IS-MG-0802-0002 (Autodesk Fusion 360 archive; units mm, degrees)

design "IS-MG-0802-0003" references "4M screw", "5 holes POWER", "SFP SLOT", "Digitus_DN-651107_LAN-Switch", "DIP Switch", "4 ports ethernet", "1 ports ethernet"
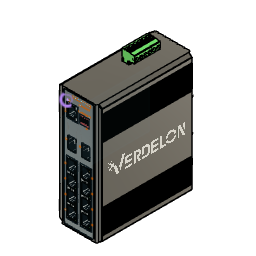
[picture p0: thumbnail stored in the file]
sketch "Sketch1" plane through (0, 0, 0) normal (0, 1, 0) x axis (1, 0, 0)
  line L1 (46, 0) -> (4, 0)
  line L2 (50, -137) -> (50, -3)
  line L3 (4, -140) -> (46, -140)
  line L4 (0, -3) -> (0, -137)
  line L5 (0, -137) -> (4, -140)
  line L6 (46, -140) -> (50, -137)
  line L7 (50, -3) -> (46, 0)
  line L8 (0, -3) -> (4, 0)
  point P1 (0, 0)
  point P2 (0, 0)
  point P5 (0, -140)
  point P4 (50, -140)
  point P3 (50, 0)
  point P6 (4, -140)
  point P7 (0, -137)
  point P8 (50, -137)
  point P9 (46, -140)
  point P10 (46, 0)
  point P11 (50, -3)
  point P12 (4, 0)
  point P13 (0, -3)
  horizontal L1
  vertical L2
  horizontal L3
  vertical L4
  coincident P1 P2
  coincident P5 L3
  coincident P5 L4
  coincident P4 L2
  coincident P4 L3
  coincident P3 L1
  coincident P3 L2
  coincident P2 L1
  coincident P2 L4
  dimension "d1" distance P2 P5 = 140
  dimension "d2" distance P2 P3 = 50
  dimension "d3" distance P5 P6 = 4
  dimension "d4" distance P5 P7 = 3
  dimension "d5" distance P4 P8 = 3
  dimension "d6" distance P4 P9 = 4
  dimension "d7" distance P3 P10 = 4
  dimension "d8" distance P3 P11 = 3
  dimension "d9" distance P2 P12 = 4
  dimension "d10" distance P2 P13 = 3
extrude "Extrude1" new body sketch "Sketch1" along normal blind 110
sketch "Sketch2" plane through (0, 0, 0) normal (0, -1, 0) x axis (1, 0, 0)
  line L1 (46, 0) -> (4, 0)
  line L2 (50, 3) -> (46, 0)
  line L3 (50, 137) -> (50, 3)
  line L4 (46, 140) -> (50, 137)
  line L5 (4, 140) -> (46, 140)
  line L6 (0, 137) -> (4, 140)
  line L7 (0, 3) -> (0, 137)
  line L8 (4, 0) -> (0, 3)
  line L9 (4, 0) -> (4, 140)
  line L10 (0, 137) -> (0, 3)
  line L11 (0, 137) -> (4, 140)
  line L12 (4, 0) -> (0, 3)
  line L13 (25, 152.2734) -> (25, 140)
  line L14 (50, 137) -> (46, 140)
  line L15 (46, 0) -> (50, 3)
  line L16 (46, 0) -> (46, 140)
  line L17 (50, 3) -> (50, 137)
  line L18 (46, 0) -> (50, 3)
  line L19 (50, 137) -> (50, 3)
  line L20 (50, 137) -> (46, 140)
  point P7 (4, 140)
  point P10 (4, 140)
  point P2 (4, 0)
  point P11 (4, 0)
  point P9 (0, 3)
  point P12 (0, 3)
  point P8 (0, 137)
  point P13 (0, 137)
  point P14 (0, 3)
  point P15 (25, 140)
  point P1 (0, 0)
  point P18 (50, 0)
  point P19 (46, 0)
  point P25 (46, 140)
  point P24 (50, 137)
  point P26 (50, 3)
  point P17 (46, 140)
  point P21 (46, 0)
  point P22 (50, 3)
  point P23 (50, 137)
  point P20 (50, 3)
  coincident P7 P10
  coincident P2 P11
  coincident P9 P12
  coincident P8 P13
  coincident P9 P14
  midpoint L5 P15
  perpendicular L5 L13
  symmetric P1 L13 P18
  symmetric P2 L13 P19
  symmetric P7 L13 P25
  symmetric P8 L13 P24
  symmetric P9 L13 P26
  symmetric P10 L13 P17
  symmetric P11 L13 P21
  symmetric P12 L13 P22
  symmetric P13 L13 P23
  symmetric P14 L13 P20
extrude "Extrude2" cut sketch "Sketch2" profile of L2 L3 L4 L6 L7 L8 L9 L10 L11 L12 L14 L15 L16 L17 L18 L19 L20 against normal blind 2
sketch "Sketch3" plane through (0, 110, 0) normal (0, 1, 0) x axis (-1, 0, 0)
  line L1 (-4, 0) -> (-46, 0)
  line L2 (0, 3) -> (-4, 0)
  line L3 (0, 137) -> (0, 3)
  line L4 (-4, 140) -> (0, 137)
  line L5 (-46, 140) -> (-4, 140)
  line L6 (-50, 137) -> (-46, 140)
  line L7 (-50, 3) -> (-50, 137)
  line L8 (-46, 0) -> (-50, 3)
  line L9 (-46, 0) -> (-46, 140)
  line L10 (-50, 3) -> (-46, 0)
  line L11 (-50, 137) -> (-50, 3)
  line L12 (-46, 140) -> (-50, 137)
  line L13 (-25, 146.5835) -> (-25, 140)
  line L14 (-4, 0) -> (0, 3)
  line L15 (0, 3) -> (-4, 0)
  line L16 (-4, 140) -> (0, 137)
  line L17 (0, 137) -> (-4, 140)
  line L18 (0, 3) -> (0, 137)
  line L19 (0, 137) -> (0, 3)
  line L20 (-4, 0) -> (-4, 140)
  point P7 (-46, 140)
  point P10 (-46, 140)
  point P2 (-46, 0)
  point P11 (-46, 0)
  point P9 (-50, 3)
  point P12 (-50, 3)
  point P8 (-50, 137)
  point P13 (-50, 137)
  point P14 (-25, 140)
  point P16 (-4, 0)
  point P19 (-4, 140)
  point P18 (0, 137)
  point P21 (0, 3)
  point P23 (-4, 140)
  point P22 (-4, 0)
  point P20 (0, 3)
  point P17 (0, 137)
  coincident P7 P10
  coincident P2 P11
  coincident P9 P12
  coincident P8 P13
  midpoint L5 P14
  perpendicular L5 L13
  symmetric P2 L13 P16
  symmetric P7 L13 P19
  symmetric P8 L13 P18
  symmetric P9 L13 P21
  symmetric P10 L13 P23
  symmetric P11 L13 P22
  symmetric P12 L13 P20
  symmetric P13 L13 P17
extrude "Extrude3" cut sketch "Sketch3" profile of L2 L3 L4 L6 L7 L8 L9 L10 L11 L12 L14 L15 L16 L17 L18 L19 L20 against normal blind 2
sketch "Sketch6" plane through (0, 2, 0) normal (0, -1, 0) x axis (1, 0, 0)
  line L1 (0, 137) -> (4, 140)
  line L2 (0, 3) -> (0, 137)
  line L3 (4, 0) -> (0, 3)
  line L4 (4, 140) -> (4, 0)
  line L5 (-20, 70) -> (0, 70)
  line L6 (50, 137) -> (0, 137)
  line L7 (25, 148.9841) -> (25, 137)
  line L8 (0, 130.5) -> (0, 131.5)
  line L9 (0, 129.4815) -> (0, 130.4815)
  line L10 (0, 128.463) -> (0, 129.463)
  line L11 (0, 127.4444) -> (0, 128.4444)
  line L12 (0, 126.4259) -> (0, 127.4259)
  line L13 (0, 125.4074) -> (0, 126.4074)
  line L14 (0, 124.3889) -> (0, 125.3889)
  line L15 (0, 123.3704) -> (0, 124.3704)
  line L16 (0, 122.3519) -> (0, 123.3519)
  line L17 (0, 121.3333) -> (0, 122.3333)
  line L18 (0, 120.3148) -> (0, 121.3148)
  line L19 (0, 119.2963) -> (0, 120.2963)
  line L20 (0, 118.2778) -> (0, 119.2778)
  line L21 (0, 117.2593) -> (0, 118.2593)
  line L22 (0, 116.2407) -> (0, 117.2407)
  line L23 (0, 115.2222) -> (0, 116.2222)
  line L24 (0, 114.2037) -> (0, 115.2037)
  line L25 (0, 113.1852) -> (0, 114.1852)
  line L26 (0, 112.1667) -> (0, 113.1667)
  line L27 (0, 111.1481) -> (0, 112.1481)
  line L28 (0, 110.1296) -> (0, 111.1296)
  line L29 (0, 109.1111) -> (0, 110.1111)
  line L30 (0, 108.0926) -> (0, 109.0926)
  line L31 (0, 107.0741) -> (0, 108.0741)
  line L32 (0, 106.0556) -> (0, 107.0556)
  line L33 (0, 105.037) -> (0, 106.037)
  line L34 (0, 104.0185) -> (0, 105.0185)
  line L35 (0, 103) -> (0, 104)
  line L36 (0, 25.7963) -> (0, 24.7963)
  line L37 (0, 13.5741) -> (0, 12.5741)
  line L38 (0, 28.8519) -> (0, 27.8519)
  line L39 (0, 27.8333) -> (0, 26.8333)
  line L40 (0, 34.963) -> (0, 33.963)
  line L41 (0, 32.9259) -> (0, 31.9259)
  line L42 (0, 30.8889) -> (0, 29.8889)
  line L43 (0, 23.7593) -> (0, 22.7593)
  line L44 (0, 29.8704) -> (0, 28.8704)
  line L45 (0, 37) -> (0, 36)
  line L46 (0, 10.5185) -> (0, 9.5185)
  line L47 (0, 31.9074) -> (0, 30.9074)
  line L48 (0, 19.6852) -> (0, 18.6852)
  line L49 (0, 35.9815) -> (0, 34.9815)
  line L50 (0, 26.8148) -> (0, 25.8148)
  line L51 (0, 16.6296) -> (0, 15.6296)
  line L52 (0, 22.7407) -> (0, 21.7407)
  line L53 (0, 33.9444) -> (0, 32.9444)
  line L54 (0, 9.5) -> (0, 8.5)
  line L55 (0, 20.7037) -> (0, 19.7037)
  line L56 (0, 18.6667) -> (0, 17.6667)
  line L57 (0, 12.5556) -> (0, 11.5556)
  line L58 (0, 15.6111) -> (0, 14.6111)
  line L59 (0, 14.5926) -> (0, 13.5926)
  line L60 (0, 11.537) -> (0, 10.537)
  line L61 (0, 21.7222) -> (0, 20.7222)
  line L62 (0, 24.7778) -> (0, 23.7778)
  line L63 (0, 17.6481) -> (0, 16.6481)
  line L64 (50, 28.8519) -> (50, 27.8519)
  line L65 (50, 32.9259) -> (50, 31.9259)
  line L66 (50, 22.7407) -> (50, 21.7407)
  line L67 (50, 31.9074) -> (50, 30.9074)
  line L68 (50, 21.7222) -> (50, 20.7222)
  line L69 (50, 29.8704) -> (50, 28.8704)
  line L70 (50, 30.8889) -> (50, 29.8889)
  line L71 (50, 25.7963) -> (50, 24.7963)
  line L72 (50, 9.5) -> (50, 8.5)
  line L73 (50, 33.9444) -> (50, 32.9444)
  line L74 (50, 24.7778) -> (50, 23.7778)
  line L75 (50, 11.537) -> (50, 10.537)
  line L76 (50, 35.9815) -> (50, 34.9815)
  line L77 (50, 23.7593) -> (50, 22.7593)
  line L78 (50, 20.7037) -> (50, 19.7037)
  line L79 (50, 34.963) -> (50, 33.963)
  line L80 (50, 26.8148) -> (50, 25.8148)
  line L81 (50, 27.8333) -> (50, 26.8333)
  line L82 (50, 18.6667) -> (50, 17.6667)
  line L83 (50, 37) -> (50, 36)
  line L84 (50, 19.6852) -> (50, 18.6852)
  line L85 (50, 15.6111) -> (50, 14.6111)
  line L86 (50, 16.6296) -> (50, 15.6296)
  line L87 (50, 10.5185) -> (50, 9.5185)
  line L88 (50, 17.6481) -> (50, 16.6481)
  line L89 (50, 12.5556) -> (50, 11.5556)
  line L90 (50, 13.5741) -> (50, 12.5741)
  line L91 (50, 14.5926) -> (50, 13.5926)
  line L92 (50, 103) -> (50, 104)
  line L93 (50, 104.0185) -> (50, 105.0185)
  line L94 (50, 105.037) -> (50, 106.037)
  line L95 (50, 121.3333) -> (50, 122.3333)
  line L96 (50, 130.5) -> (50, 131.5)
  line L97 (50, 120.3148) -> (50, 121.3148)
  line L98 (50, 118.2778) -> (50, 119.2778)
  line L99 (50, 126.4259) -> (50, 127.4259)
  line L100 (50, 110.1296) -> (50, 111.1296)
  line L101 (50, 114.2037) -> (50, 115.2037)
  line L102 (50, 111.1481) -> (50, 112.1481)
  line L103 (50, 123.3704) -> (50, 124.3704)
  line L104 (50, 115.2222) -> (50, 116.2222)
  line L105 (50, 116.2407) -> (50, 117.2407)
  line L106 (50, 124.3889) -> (50, 125.3889)
  line L107 (50, 127.4444) -> (50, 128.4444)
  line L108 (50, 119.2963) -> (50, 120.2963)
  line L109 (50, 109.1111) -> (50, 110.1111)
  line L110 (50, 113.1852) -> (50, 114.1852)
  line L111 (50, 128.463) -> (50, 129.463)
  line L112 (50, 125.4074) -> (50, 126.4074)
  line L113 (50, 112.1667) -> (50, 113.1667)
  line L114 (50, 107.0741) -> (50, 108.0741)
  line L115 (50, 108.0926) -> (50, 109.0926)
  line L116 (50, 129.4815) -> (50, 130.4815)
  line L117 (50, 122.3519) -> (50, 123.3519)
  line L118 (50, 117.2593) -> (50, 118.2593)
  line L119 (50, 106.0556) -> (50, 107.0556)
  arc A1 centre (0, 131) radius 0.5 clockwise from (0, 131.5) to (0, 130.5)
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  point P6 (0, 70)
  point P3 (0, 137)
  point P8 (0, 137)
  point P10 (25, 137)
  point P12 (0, 131)
  point P13 (0, 131.5)
  point P14 (0, 130.5)
  point P149 (0, 8.5)
  point P159 (0, 9.5)
  point P16 (0, 129.4815)
  point P137 (0, 10.5185)
  point P17 (0, 130.4815)
  point P132 (0, 9.5185)
  point P19 (0, 128.463)
  point P147 (0, 11.537)
  point P20 (0, 129.463)
  point P176 (0, 10.537)
  point P22 (0, 127.4444)
  point P112 (0, 12.5556)
  point P23 (0, 128.4444)
  point P110 (0, 11.5556)
  point P25 (0, 126.4259)
  point P99 (0, 13.5741)
  point P26 (0, 127.4259)
  point P165 (0, 12.5741)
  point P28 (0, 125.4074)
  point P157 (0, 14.5926)
  point P29 (0, 126.4074)
  point P163 (0, 13.5926)
  point P31 (0, 124.3889)
  point P166 (0, 15.6111)
  point P32 (0, 125.3889)
  point P160 (0, 14.6111)
  point P34 (0, 123.3704)
  point P155 (0, 16.6296)
  point P35 (0, 124.3704)
  point P161 (0, 15.6296)
  point P37 (0, 122.3519)
  point P156 (0, 17.6481)
  point P38 (0, 123.3519)
  point P97 (0, 16.6481)
  point P40 (0, 121.3333)
  point P98 (0, 18.6667)
  point P41 (0, 122.3333)
  point P115 (0, 17.6667)
  point P43 (0, 120.3148)
  point P109 (0, 19.6852)
  point P44 (0, 121.3148)
  point P143 (0, 18.6852)
  point P46 (0, 119.2963)
  point P139 (0, 20.7037)
  point P47 (0, 120.2963)
  point P124 (0, 19.7037)
  point P49 (0, 118.2778)
  point P123 (0, 21.7222)
  point P50 (0, 119.2778)
  point P108 (0, 20.7222)
  point P52 (0, 117.2593)
  point P105 (0, 22.7407)
  point P53 (0, 118.2593)
  point P167 (0, 21.7407)
  point P55 (0, 116.2407)
  point P106 (0, 23.7593)
  point P56 (0, 117.2407)
  point P107 (0, 22.7593)
  point P58 (0, 115.2222)
  point P104 (0, 24.7778)
  point P59 (0, 116.2222)
  point P96 (0, 23.7778)
  point P61 (0, 114.2037)
  point P130 (0, 25.7963)
  point P62 (0, 115.2037)
  point P125 (0, 24.7963)
  point P64 (0, 113.1852)
  point P126 (0, 26.8148)
  point P65 (0, 114.1852)
  point P121 (0, 25.8148)
  point P67 (0, 112.1667)
  point P127 (0, 27.8333)
  point P68 (0, 113.1667)
  point P134 (0, 26.8333)
  point P70 (0, 111.1481)
  point P138 (0, 28.8519)
  point P71 (0, 112.1481)
  point P140 (0, 27.8519)
  point P73 (0, 110.1296)
  point P142 (0, 29.8704)
  point P74 (0, 111.1296)
  point P133 (0, 28.8704)
  point P76 (0, 109.1111)
  point P154 (0, 30.8889)
  point P77 (0, 110.1111)
  point P151 (0, 29.8889)
  point P79 (0, 108.0926)
  point P153 (0, 31.9074)
  point P80 (0, 109.0926)
  point P168 (0, 30.9074)
  point P82 (0, 107.0741)
  point P171 (0, 32.9259)
  point P83 (0, 108.0741)
  point P175 (0, 31.9259)
  point P85 (0, 106.0556)
  point P172 (0, 33.9444)
  point P86 (0, 107.0556)
  point P146 (0, 32.9444)
  point P88 (0, 105.037)
  point P141 (0, 34.963)
  point P89 (0, 106.037)
  point P131 (0, 33.963)
  point P91 (0, 104.0185)
  point P129 (0, 35.9815)
  point P92 (0, 105.0185)
  point P119 (0, 34.9815)
  point P94 (0, 103)
  point P179 (0, 37)
  point P95 (0, 104)
  point P103 (0, 36)
  point P331 (50, 131.5)
  point P289 (50, 130.5)
  point P341 (50, 129.4815)
  point P324 (50, 130.4815)
  point P320 (50, 128.463)
  point P325 (50, 129.463)
  point P282 (50, 127.4444)
  point P294 (50, 128.4444)
  point P300 (50, 126.4259)
  point P298 (50, 127.4259)
  point P313 (50, 125.4074)
  point P318 (50, 126.4074)
  point P315 (50, 124.3889)
  point P283 (50, 125.3889)
  point P286 (50, 123.3704)
  point P287 (50, 124.3704)
  point P280 (50, 122.3519)
  point P322 (50, 123.3519)
  point P305 (50, 121.3333)
  point P321 (50, 122.3333)
  point P310 (50, 120.3148)
  point P311 (50, 121.3148)
  point P309 (50, 119.2963)
  point P306 (50, 120.2963)
  point P312 (50, 118.2778)
  point P266 (50, 119.2778)
  point P271 (50, 117.2593)
  point P265 (50, 118.2593)
  point P269 (50, 116.2407)
  point P264 (50, 117.2407)
  point P270 (50, 115.2222)
  point P272 (50, 116.2222)
  point P268 (50, 114.2037)
  point P267 (50, 115.2037)
  point P274 (50, 113.1852)
  point P273 (50, 114.1852)
  point P278 (50, 112.1667)
  point P277 (50, 113.1667)
  point P279 (50, 111.1481)
  point P276 (50, 112.1481)
  point P342 (50, 110.1296)
  point P275 (50, 111.1296)
  point P319 (50, 109.1111)
  point P303 (50, 110.1111)
  point P299 (50, 108.0926)
  point P301 (50, 109.0926)
  point P297 (50, 107.0741)
  point P291 (50, 108.0741)
  point P292 (50, 106.0556)
  point P296 (50, 107.0556)
  point P316 (50, 105.037)
  point P317 (50, 106.037)
  point P284 (50, 104.0185)
  point P281 (50, 105.0185)
  point P285 (50, 103)
  point P323 (50, 104)
  point P186 (50, 23.7778)
  point P199 (50, 16.6481)
  point P191 (50, 18.6667)
  point P242 (50, 13.5741)
  point P187 (50, 36)
  point P207 (50, 24.7778)
  point P202 (50, 22.7407)
  point P195 (50, 23.7593)
  point P192 (50, 22.7593)
  point P197 (50, 20.7222)
  point P229 (50, 19.6852)
  point P222 (50, 11.5556)
  point P230 (50, 12.5556)
  point P238 (50, 17.6667)
  point P180 (50, 34.9815)
  point P198 (50, 25.8148)
  point P196 (50, 21.7222)
  point P228 (50, 19.7037)
  point P215 (50, 24.7963)
  point P220 (50, 26.8148)
  point P221 (50, 27.8333)
  point P224 (50, 35.9815)
  point P243 (50, 25.7963)
  point P217 (50, 33.963)
  point P253 (50, 9.5185)
  point P209 (50, 28.8704)
  point P240 (50, 26.8333)
  point P234 (50, 10.5185)
  point P225 (50, 28.8519)
  point P231 (50, 20.7037)
  point P241 (50, 27.8519)
  point P239 (50, 34.963)
  point P218 (50, 29.8704)
  point P210 (50, 18.6852)
  point P216 (50, 32.9444)
  point P254 (50, 11.537)
  point P255 (50, 8.5)
  point P204 (50, 29.8889)
  point P203 (50, 31.9074)
  point P201 (50, 30.8889)
  point P256 (50, 16.6296)
  point P213 (50, 17.6481)
  point P214 (50, 14.5926)
  point P261 (50, 9.5)
  point P263 (50, 14.6111)
  point P260 (50, 15.6296)
  point P262 (50, 13.5926)
  point P258 (50, 12.5741)
  point P259 (50, 15.6111)
  point P205 (50, 21.7407)
  point P208 (50, 30.9074)
  point P200 (50, 32.9259)
  point P206 (50, 33.9444)
  point P182 (50, 31.9259)
  point P257 (50, 10.537)
  point P184 (50, 37)
  midpoint L2 P6
  perpendicular L2 L5
  coincident P3 P8
  perpendicular L4 L6
  midpoint L6 P10
  perpendicular L6 L7
  coincident L2 P12
  coincident L2 P13
  coincident L2 P14
  symmetric L5 P13 P149
  symmetric L5 P14 P159
  symmetric L5 P16 P137
  symmetric L5 P17 P132
  symmetric L5 P19 P147
  symmetric L5 P20 P176
  symmetric L5 P22 P112
  symmetric L5 P23 P110
  symmetric L5 P25 P99
  symmetric L5 P26 P165
  symmetric L5 P28 P157
  symmetric L5 P29 P163
  symmetric L5 P31 P166
  symmetric L5 P32 P160
  symmetric L5 P34 P155
  symmetric L5 P35 P161
  symmetric L5 P37 P156
  symmetric L5 P38 P97
  symmetric L5 P40 P98
  symmetric L5 P41 P115
  symmetric L5 P43 P109
  symmetric L5 P44 P143
  symmetric L5 P46 P139
  symmetric L5 P47 P124
  symmetric L5 P49 P123
  symmetric L5 P50 P108
  symmetric L5 P52 P105
  symmetric L5 P53 P167
  symmetric L5 P55 P106
  symmetric L5 P56 P107
  symmetric L5 P58 P104
  symmetric L5 P59 P96
  symmetric L5 P61 P130
  symmetric L5 P62 P125
  symmetric L5 P64 P126
  symmetric L5 P65 P121
  symmetric L5 P67 P127
  symmetric L5 P68 P134
  symmetric L5 P70 P138
  symmetric L5 P71 P140
  symmetric L5 P73 P142
  symmetric L5 P74 P133
  symmetric L5 P76 P154
  symmetric L5 P77 P151
  symmetric L5 P79 P153
  symmetric L5 P80 P168
  symmetric L5 P82 P171
  symmetric L5 P83 P175
  symmetric L5 P85 P172
  symmetric L5 P86 P146
  symmetric L5 P88 P141
  symmetric L5 P89 P131
  symmetric L5 P91 P129
  symmetric L5 P92 P119
  symmetric L5 P94 P179
  symmetric L5 P95 P103
  symmetric L7 P13 P331
  symmetric L7 P14 P289
  symmetric L7 P16 P341
  symmetric L7 P17 P324
  symmetric L7 P19 P320
  symmetric L7 P20 P325
  symmetric L7 P22 P282
  symmetric L7 P23 P294
  symmetric L7 P25 P300
  symmetric L7 P26 P298
  symmetric L7 P28 P313
  symmetric L7 P29 P318
  symmetric L7 P31 P315
  symmetric L7 P32 P283
  symmetric L7 P34 P286
  symmetric L7 P35 P287
  symmetric L7 P37 P280
  symmetric L7 P38 P322
  symmetric L7 P40 P305
  symmetric L7 P41 P321
  symmetric L7 P43 P310
  symmetric L7 P44 P311
  symmetric L7 P46 P309
  symmetric L7 P47 P306
  symmetric L7 P49 P312
  symmetric L7 P50 P266
  symmetric L7 P52 P271
  symmetric L7 P53 P265
  symmetric L7 P55 P269
  symmetric L7 P56 P264
  symmetric L7 P58 P270
  symmetric L7 P59 P272
  symmetric L7 P61 P268
  symmetric L7 P62 P267
  symmetric L7 P64 P274
  symmetric L7 P65 P273
  symmetric L7 P67 P278
  symmetric L7 P68 P277
  symmetric L7 P70 P279
  symmetric L7 P71 P276
  symmetric L7 P73 P342
  symmetric L7 P74 P275
  symmetric L7 P76 P319
  symmetric L7 P77 P303
  symmetric L7 P79 P299
  symmetric L7 P80 P301
  symmetric L7 P82 P297
  symmetric L7 P83 P291
  symmetric L7 P85 P292
  symmetric L7 P86 P296
  symmetric L7 P88 P316
  symmetric L7 P89 P317
  symmetric L7 P91 P284
  symmetric L7 P92 P281
  symmetric L7 P94 P285
  symmetric L7 P95 P323
  symmetric L7 P96 P186
  symmetric L7 P97 P199
  symmetric L7 P98 P191
  symmetric L7 P99 P242
  symmetric L7 P103 P187
  symmetric L7 P104 P207
  symmetric L7 P105 P202
  symmetric L7 P106 P195
  symmetric L7 P107 P192
  symmetric L7 P108 P197
  symmetric L7 P109 P229
  symmetric L7 P110 P222
  symmetric L7 P112 P230
  symmetric L7 P115 P238
  symmetric L7 P119 P180
  symmetric L7 P121 P198
  symmetric L7 P123 P196
  symmetric L7 P124 P228
  symmetric L7 P125 P215
  symmetric L7 P126 P220
  symmetric L7 P127 P221
  symmetric L7 P129 P224
  symmetric L7 P130 P243
  symmetric L7 P131 P217
  symmetric L7 P132 P253
  symmetric L7 P133 P209
  symmetric L7 P134 P240
  symmetric L7 P137 P234
  symmetric L7 P138 P225
  symmetric L7 P139 P231
  symmetric L7 P140 P241
  symmetric L7 P141 P239
  symmetric L7 P142 P218
  symmetric L7 P143 P210
  symmetric L7 P146 P216
  symmetric L7 P147 P254
  symmetric L7 P149 P255
  symmetric L7 P151 P204
  symmetric L7 P153 P203
  symmetric L7 P154 P201
  symmetric L7 P155 P256
  symmetric L7 P156 P213
  symmetric L7 P157 P214
  symmetric L7 P159 P261
  symmetric L7 P160 P263
  symmetric L7 P161 P260
  symmetric L7 P163 P262
  symmetric L7 P165 P258
  symmetric L7 P166 P259
  symmetric L7 P167 P205
  symmetric L7 P168 P208
  symmetric L7 P171 P200
  symmetric L7 P172 P206
  symmetric L7 P175 P182
  symmetric L7 P176 P257
  symmetric L7 P179 P184
  dimension "d54" diameter A1 = 1
  dimension "d59" distance L5 P94 = 33
  dimension "d57" R-Pattern1-uDistance = 0
  dimension "d58" R-Pattern1-vDistance = -27.5
extrude "Extrude6" cut sketch "Sketch6" against normal blind 140
fillet "Fillet2" radius 2
fillet "Fillet3" radius 0.5
sketch "Sketch4" plane through (0, 0, 0) normal (0, -1, 0) x axis (1, 0, 0)
  line L1 (6, 0) -> (6, 140)
  line L2 (44, 0) -> (6, 0)
  line L3 (44, 140) -> (44, 0)
  line L4 (6, 140) -> (44, 140)
  line L5 (40.5, 1.5) -> (9.5, 1.5)
  line L6 (42.5, 136.5) -> (42.5, 3.5)
  line L7 (9.5, 138.5) -> (40.5, 138.5)
  line L8 (7.5, 3.5) -> (7.5, 136.5)
  line L9 (40.5, 2) -> (9.5, 2)
  line L10 (42, 136.5) -> (42, 3.5)
  line L11 (9.5, 138) -> (40.5, 138)
  line L12 (8, 3.5) -> (8, 136.5)
  arc A1 centre (9.5, 136.5) radius 2 clockwise from (7.5, 136.5) to (9.5, 138.5)
  arc A2 centre (40.5, 136.5) radius 2 clockwise from (40.5, 138.5) to (42.5, 136.5)
  arc A3 centre (9.5, 3.5) radius 2 clockwise from (9.5, 1.5) to (7.5, 3.5)
  arc A4 centre (40.5, 3.5) radius 2 clockwise from (42.5, 3.5) to (40.5, 1.5)
  arc A5 centre (40.5, 3.5) radius 1.5 clockwise from (42, 3.5) to (40.5, 2)
  arc A6 centre (40.5, 136.5) radius 1.5 clockwise from (40.5, 138) to (42, 136.5)
  arc A7 centre (9.5, 136.5) radius 1.5 clockwise from (8, 136.5) to (9.5, 138)
  arc A8 centre (9.5, 3.5) radius 1.5 clockwise from (9.5, 2) to (8, 3.5)
  tangent L7 A1
  tangent L8 A1
  tangent L6 A2
  tangent L7 A2
  equal A1 A2
  tangent L5 A3
  tangent L8 A3
  equal A1 A3
  tangent L5 A4
  tangent L6 A4
  equal A1 A4
  dimension "d26" radius A1 = 2
  dimension "d27" = -0.5
extrude "Extrude4" cut sketch "Sketch4" profile of L7 L6 L5 L8 A1 A2 A3 A4 A8 A7 L9 A5 L10 A6 L12 L11 against normal blind 0.1
sketch "Sketch5" plane through (0, 0, 0) normal (0, -1, 0) x axis (1, 0, 0)
  line L1 (8, 3.5) -> (8, 136.5)
  line L2 (40.5, 2) -> (9.5, 2)
  line L3 (42, 136.5) -> (42, 3.5)
  line L4 (9.5, 138) -> (40.5, 138)
  line L5 (25, 70) -> (25, 138)
  line L6 (25, 70) -> (8, 70)
  line L7 (23.5, 8.2) -> (10.34, 8.2)
  line L8 (23.5, 72) -> (23.5, 8.2)
  line L9 (10.34, 72) -> (23.5, 72)
  line L10 (10.34, 8.2) -> (10.34, 72)
  line L11 (39.66, 8.2) -> (26.5, 8.2)
  line L12 (39.66, 72) -> (39.66, 8.2)
  line L13 (26.5, 72) -> (39.66, 72)
  line L14 (26.5, 8.2) -> (26.5, 72)
  line L15 (21.02, 79) -> (12.82, 79)
  line L16 (21.77, 92.75) -> (21.77, 79.75)
  line L17 (12.82, 93.5) -> (21.02, 93.5)
  line L18 (12.07, 79.75) -> (12.07, 92.75)
  line L19 (16.92, 75) -> (16.92, 79)
  line L20 (28.23, 92.75) -> (28.23, 79.75)
  line L21 (37.18, 93.5) -> (28.98, 93.5)
  line L22 (37.93, 79.75) -> (37.93, 92.75)
  line L23 (28.98, 79) -> (37.18, 79)
  line L24 (24, 127) -> (10.84, 127)
  line L25 (24, 110.59) -> (24, 127)
  line L26 (10.84, 110.59) -> (24, 110.59)
  line L27 (10.84, 127) -> (10.84, 110.59)
  line L28 (37, 111.59) -> (26, 111.59)
  line L29 (37, 121.59) -> (37, 111.59)
  line L30 (26, 121.59) -> (37, 121.59)
  line L31 (26, 111.59) -> (26, 121.59)
  arc A1 centre (9.5, 3.5) radius 1.5 clockwise from (9.5, 2) to (8, 3.5)
  arc A2 centre (40.5, 3.5) radius 1.5 clockwise from (42, 3.5) to (40.5, 2)
  arc A3 centre (40.5, 136.5) radius 1.5 clockwise from (40.5, 138) to (42, 136.5)
  arc A4 centre (9.5, 136.5) radius 1.5 clockwise from (8, 136.5) to (9.5, 138)
  arc A5 centre (37.18, 79.75) radius 0.75 clockwise from (37.93, 79.75) to (37.18, 79)
  arc A6 centre (37.18, 92.75) radius 0.75 clockwise from (37.18, 93.5) to (37.93, 92.75)
  arc A7 centre (28.98, 92.75) radius 0.75 clockwise from (28.23, 92.75) to (28.98, 93.5)
  arc A8 centre (28.98, 79.75) radius 0.75 clockwise from (28.98, 79) to (28.23, 79.75)
  arc A9 centre (21.02, 79.75) radius 0.75 clockwise from (21.77, 79.75) to (21.02, 79)
  arc A10 centre (12.82, 79.75) radius 0.75 clockwise from (12.82, 79) to (12.07, 79.75)
  arc A11 centre (12.82, 92.75) radius 0.75 clockwise from (12.07, 92.75) to (12.82, 93.5)
  arc A12 centre (21.02, 92.75) radius 0.75 clockwise from (21.02, 93.5) to (21.77, 92.75)
  circle C1 centre (11.84, 129) radius 0.5
  point P14 (25, 138)
  point P15 (8, 70)
  point P28 (16.92, 79)
  point P25 (12.07, 79)
  point P27 (12.07, 93.5)
  point P26 (21.77, 93.5)
  point P17 (10.34, 8.2)
  point P20 (10.34, 72)
  point P19 (23.5, 72)
  point P22 (39.66, 8.2)
  point P23 (39.66, 72)
  point P24 (26.5, 72)
  point P30 (10.84, 127)
  point P33 (10.84, 110.59)
  point P31 (24, 127)
  point P36 (37, 121.59)
  point P37 (26, 121.59)
  point P35 (37, 111.59)
  point P62 (11.84, 129)
  midpoint L4 P14
  perpendicular L4 L5
  midpoint L1 P15
  perpendicular L5 L6
  horizontal L7
  vertical L8
  horizontal L9
  vertical L10
  horizontal L11
  vertical L12
  horizontal L13
  vertical L14
  collinear L9 L13
  horizontal L15
  vertical L16
  horizontal L17
  vertical L18
  perpendicular L15 L19
  symmetric L8 L10 L19
  horizontal L24
  vertical L25
  horizontal L26
  vertical L27
  horizontal L28
  vertical L29
  horizontal L30
  vertical L31
  tangent L22 A5
  tangent L23 A5
  tangent L21 A6
  tangent L22 A6
  equal A5 A6
  tangent L20 A7
  tangent L21 A7
  equal A5 A7
  tangent L20 A8
  tangent L23 A8
  equal A5 A8
  coincident L15 P28
  tangent L15 A9
  tangent L16 A9
  equal A5 A9
  coincident P25 L15
  coincident P25 L18
  tangent L15 A10
  tangent L18 A10
  equal A5 A10
  coincident P27 L17
  coincident P27 L18
  tangent L17 A11
  tangent L18 A11
  equal A5 A11
  coincident P26 L16
  coincident P26 L17
  tangent L16 A12
  tangent L17 A12
  equal A5 A12
  collinear L17 L21
  collinear L15 L23
  dimension "d30" distance P17 P20 = 63.8
  dimension "d31" distance P19 P20 = 13.16
  dimension "d32" distance P22 P23 = 63.8
  dimension "d33" distance P23 P24 = 13.16
  dimension "d34" distance L5 P19 = 1.5
  dimension "d35" distance L5 L14 = 1.5
  dimension "d37" distance P25 P27 = 14.5
  dimension "d38" distance P26 P27 = 9.7
  dimension "d39" distance L6 L9 = 2
  dimension "d40" distance L9 L15 = 7
  dimension "d41" distance P30 P33 = 16.41
  dimension "d42" distance P30 P31 = 13.16
  dimension "d43" distance P36 P37 = 11
  dimension "d44" distance P35 P36 = 10
  dimension "d45" distance L26 L28 = 1
  dimension "d46" distance L5 L25 = 1
  dimension "d47" distance P14 L24 = 11
  dimension "d48" distance L5 L31 = 1
  dimension "d52" radius A5 = 0.75
  dimension "d84" distance L5 L16 = 3.23
  dimension "d85" distance L5 L20 = 3.23
  dimension "d86" distance L20 L22 = 9.7
  dimension "d116" diameter C1 = 1
  dimension "d117" distance L27 P62 = 1
  dimension "d118" distance L24 P62 = 2
extrude "Extrude5" cut sketch "Sketch5" profile of L6 L7 L8 L9 L10 L11 L12 L13 L14 L15 L16 L17 L18 L20 L21 L22 L23 L24 L25 L26 L27 L28 L29 L30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 against normal blind 5
shell "Shell3" innerThickness 1
sketch "Sketch7" plane through (0, 0, 0) normal (-1, 0, 0) x axis (0, -1, 0)
  line L1 (-107.5, 37) -> (-107.5, 103)
  line L2 (-2.5, 37) -> (-107.5, 37)
  line L3 (-2.5, 103) -> (-2.5, 37)
  line L4 (-107.5, 103) -> (-2.5, 103)
  line L5 (-110, 0) -> (-110, 140)
  line L6 (-107.5, 140) -> (-2.5, 140)
  line L7 (-55, 70) -> (-55, 140)
  line L8 (-55, 70) -> (-107.5, 70)
  circle C1 centre (-100, 120) radius 2
  circle C2 centre (-10, 120) radius 2
  circle C3 centre (-100, 20) radius 2
  circle C4 centre (-10, 20) radius 2
  point P11 (-55, 140)
  point P12 (-107.5, 70)
  point P6 (-100, 120)
  midpoint L6 P11
  perpendicular L6 L7
  midpoint L1 P12
  perpendicular L7 L8
  symmetric C1 L7 C2
  symmetric C1 L8 C3
  symmetric L8 C2 C4
  dimension "d63" diameter C1 = 4
  dimension "d64" distance P6 L5 = 10
  dimension "d65" distance P6 L6 = 20
extrude "Extrude7" cut sketch "Sketch7" profile of C1 C2 C3 C4 against normal blind 3
sketch "Sketch10" plane through (0, 0, 140) normal (0, 0, 1) x axis (-1, 0, 0)
  line L1 (-6, -110) -> (-44, -110)
  line L2 (-4, -2.5) -> (-4, -107.5)
  line L3 (-44, 0) -> (-6, 0)
  line L4 (-46, -107.5) -> (-46, -2.5)
  line L5 (-25, -55) -> (-25, -110)
  line L6 (-25, -55) -> (-4, -55)
  line L7 (-23, -90) -> (-15.33, -90)
  line L8 (-23, -60) -> (-23, -90)
  line L9 (-15.33, -60) -> (-23, -60)
  line L10 (-15.33, -90) -> (-15.33, -60)
  closed curve K1 centre (-45.1667, -107.5)
  arc A1 centre (-44, -108) radius 2 clockwise from (-44, -110) to (-45.9672, -107.639)
  arc A2 centre (-6, -108) radius 2 clockwise from (-4.0328, -107.639) to (-6, -110)
  closed curve K2 centre (-4.8333, -107.5)
  closed curve K3 centre (-4.8333, -2.5)
  arc A3 centre (-6, -2) radius 2 clockwise from (-6, 0) to (-4.0328, -2.361)
  arc A4 centre (-44, -2) radius 2 clockwise from (-45.9672, -2.361) to (-44, 0)
  closed curve K4 centre (-45.1667, -2.5)
  point P22 (-25, -110)
  point P23 (-4, -55)
  point P25 (-15.33, -90)
  point P28 (-15.33, -60)
  point P26 (-23, -90)
  midpoint L1 P22
  perpendicular L1 L5
  midpoint L2 P23
  perpendicular L2 L6
  horizontal L7
  vertical L8
  horizontal L9
  vertical L10
  dimension "d95" distance P25 P28 = 30
  dimension "d96" distance P25 P26 = 7.67
  dimension "d97" distance L6 L9 = 5
  dimension "d98" distance L5 L8 = 2
extrude "Extrude8" cut sketch "Sketch10" profile of L7 L8 L9 L10 against normal blind 10
component_insert "Component Insert6"
joint "Assemble1" alignAngle 0 alignOffsetX 0 alignOffsetY 0 alignOffsetZ 0
sketch "Sketch8" plane through (0, 0, 0) normal (-1, 0, 0) x axis (0, -1, 0)
  line L1 (-107.5, 37) -> (-107.5, 103)
  line L2 (-2.5, 37) -> (-107.5, 37)
  line L3 (-2.5, 103) -> (-2.5, 37)
  line L4 (-107.5, 103) -> (-2.5, 103)
rectangular_pattern "00000000-0000-0000-0000-000000000000" uSpaceDistance -90 vSpaceDistance 0
rectangular_pattern "00000000-0000-0000-0000-000000000000" uSpaceDistance 100 vSpaceDistance 0
component_insert "Component Insert11"
position "Position2"
rectangular_pattern "00000000-0000-0000-0000-000000000000" uSpaceDistance 16.15 vSpaceDistance 0
component_insert "Component Insert12"
component_insert "Component Insert13"
position "Position3"
component_insert "Component Insert15"
position "Position4"
component_insert "Component Insert18"
position "Position5"
rectangular_pattern "00000000-0000-0000-0000-000000000000" uSpaceDistance -16.16 vSpaceDistance 0
sketch "Sketch11" plane through (0, 0, 0) normal (0, -1, 0) x axis (1, 0, 0)
  dimension "d101" = 1
  dimension "d102" = 1
  dimension "d103" = 1
  dimension "d104" = 1
  dimension "d105" = 1
  dimension "d106" = 1
  dimension "d107" = 1
  dimension "d108" = 1
  dimension "d109" = 1
  dimension "d110" = 1
  dimension "d111" = 1
  dimension "d112" = 1
  dimension "d113" = 1
  dimension "d114" = 1
  dimension "d115" = 1.3
  dimension "d119" = 1
decal "Decal1"
decal "Decal2"
component_insert "Component Insert16"
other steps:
joint_origin "JointOrigin1"

design "5 holes POWER"
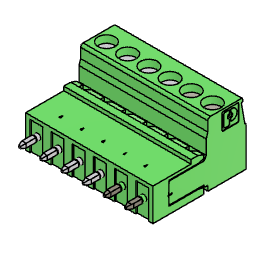
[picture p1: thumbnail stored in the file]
description: STEP AP214
part number: POWER

design "DIP Switch"
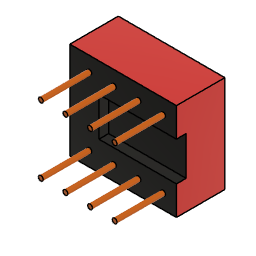
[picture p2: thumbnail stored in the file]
description: STEP AP214
part number: DIP Switch

design "4 ports ethernet"
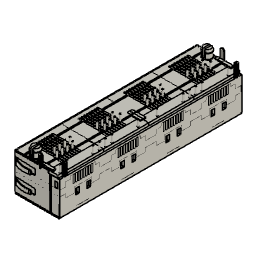
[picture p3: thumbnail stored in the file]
description: STEP AP214
part number: 4 ports ethernet

design "Digitus_DN-651107_LAN-Switch"
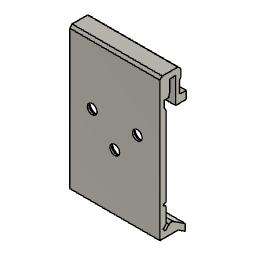
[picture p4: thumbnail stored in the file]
description: STEP AP214
part number: Digitus_DN-651107_LAN-Switch

design "1 ports ethernet"
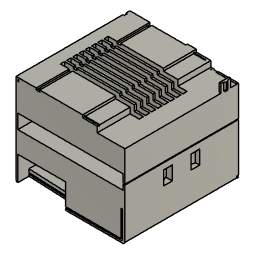
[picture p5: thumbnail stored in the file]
description: STEP AP214
part number: 1 ports ethernet

design "4M screw"
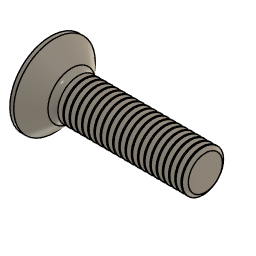
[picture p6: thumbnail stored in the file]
description: STEP AP214
part number: screw

design "SFP SLOT"
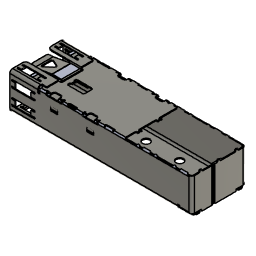
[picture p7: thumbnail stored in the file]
description: STEP AP214
part number: SFP SLOT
